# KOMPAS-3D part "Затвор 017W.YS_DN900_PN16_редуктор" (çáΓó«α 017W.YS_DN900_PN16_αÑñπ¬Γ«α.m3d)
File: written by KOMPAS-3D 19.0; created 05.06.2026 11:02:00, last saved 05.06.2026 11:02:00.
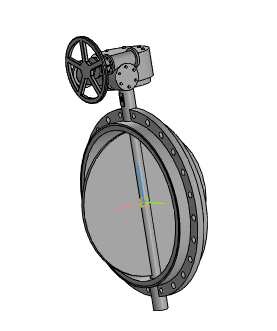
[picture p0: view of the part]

Document properties: Автор: Энергия; Полное имя файла: ..\..\..\3d для проектировщиков\x.x Тип 017W.Y(S) Затвор дисковый поворотный межфланцевый\Затвор 017W.Y(S)_DN50-DN1200_редуктор\Затвор 017W.YS_DN900_PN16_редуктор.a3d

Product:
- Part/product: Затвор 017W.YS_DN900_PN16_редуктор
    Масса: 579.494

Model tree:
1. Операция без истории:1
